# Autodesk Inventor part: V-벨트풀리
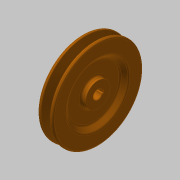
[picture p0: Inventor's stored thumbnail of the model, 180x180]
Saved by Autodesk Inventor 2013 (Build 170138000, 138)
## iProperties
Created: 2015-12
Part Number: V-벨트풀리
Document SubType Name: Modeling
Designer: mdu
Density: 8.08 g/cm^3
Material: 스테인리스강
Author: mdu
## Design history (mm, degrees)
sketch "스케치1"
  geometry: L1 (-10, 0)-(10, 0); L2 (-10, 0)-(-10, 16); L3 (-10, 16)-(-4, 16); L4 (-4, 16)-(-4, 35); L5 (-4, 35)-(-10, 41); L6 (-10, 41)-(-10, 59.5); L7 (-10, 59.5)-(-6.062, 59.5); L8 (-6.062, 59.5)-(-2.001, 47); L9 (-2.001, 47)-(2.001, 47); L10 (2.001, 47)-(6.062, 59.5); L11 (6.062, 59.5)-(10, 59.5); L12 (10, 59.5)-(10, 41); L13 (10, 41)-(4, 35); L14 (4, 35)-(4, 16); L15 (4, 16)-(10, 16); L16 (10, 16)-(10, 0); L17 (-4.6, 55)-(4.6, 55); 2 further points
  constraints: 34 end point, 7 parallel, 6 equal length, 5 collinear, 3 perpendicular, 2 point on line, 1 coincident, 1 horizontal, 1 midpoint
  dimensions: "d0" = 20 distance of L1.start L1.end; "d1" = 9.2 distance of L17.start L17.end; "d2" = 36 deg angle of L10 L8; "d3" = 4.5 distance between parallel lines of L7 L17; "d4" = 8 distance between parallel lines of L9 L17; "d6" = 110 diameter of L17 L1; "d7" = 32 diameter of L3 L1; "d8" = 82 diameter of L5.end L1; "d9" = 6 distance of L2.end L3.end; "d10" = 135 deg angle of L4 L5
revolve "회전1" sketch "스케치1" stored, may be unused: angle "d11" = 90 deg
fillet "모깎기1" dims "d12" = 2, "d13" = 0.5, "d14" = 1, "d15" = 3
sketch "스케치2"
  geometry: L1 (-2, 5.657)-(-2, 7.8); L2 (-2, 7.8)-(2, 7.8); L3 (2, 7.8)-(2, 5.657); A1 r 6 centre (0, 0) between (-2, 5.657) and (2, 5.657); 1 further point
  constraints: 6 end point, 2 parallel, 2 point on circle, 1 centre point, 1 coincident, 1 perpendicular, 1 vertical
  dimensions: "d16" = 12 diameter of A1; "d17" = 4 distance of L1.end L2.end; "d18" = 13.8 dimension on A1 L2 (computed from d16)
extrude "돌출1" cut sketch "스케치2" stored distance "d19" = 10; taper "d20" = 0 deg
chamfer "모따기2" distance "d24" = 0.5; stored, may be unused: second distance "d25" = 2, angle "d26" = 45 deg
sketch "스케치3" dims "d27" = 100
  geometry: C1 r 2.5 at (0, 50); 2 further points
  constraints: 2 vertical alignment, 1 centre point, 1 coincident, 2 other
  dimensions: "d28" = 5 diameter of C1
extrude "돌출2" join sketch "스케치3" distance "d29" = 1; taper "d30" = 0 deg
node "솔리드1"
